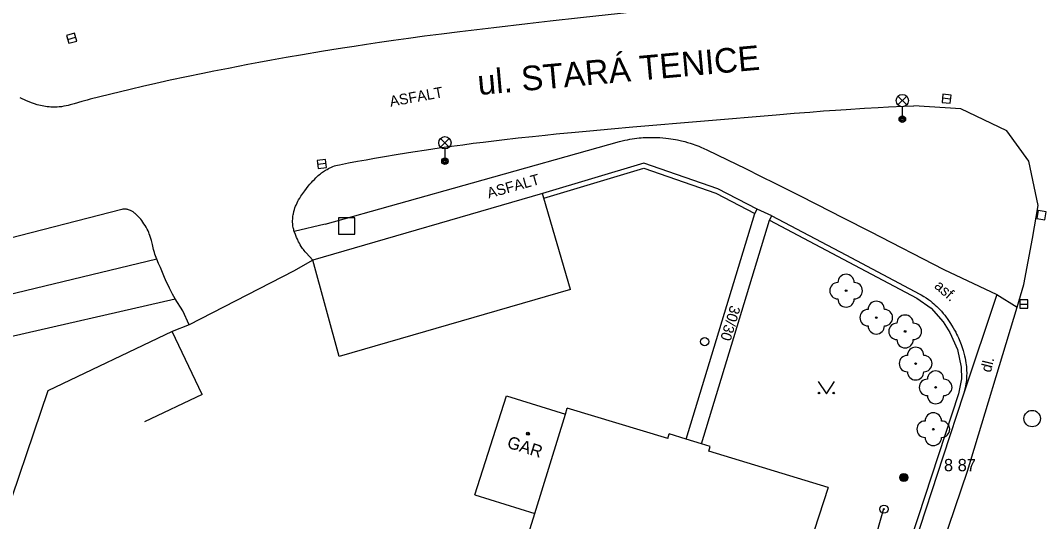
# Model space of a CAD drawing. Extents: x -538441 to -536770, y -1181008 to -1179809.
# Drawn here: x -538155.1 to -538092.8, y -1180657.4 to -1180626.8 of the extents above; entities that cross this region are included whole.
import ezdxf

# ---------------------------------------------------------------- set-up
doc = ezdxf.new("R2010")
doc.units = 0
for name, color, linetype in [('Vrstva 10', 7, 'Continuous'), ('Vrstva 11', 7, 'Continuous'), ('Vrstva 22', 7, 'Continuous'), ('Vrstva 25', 7, 'Continuous'), ('Vrstva 26', 7, 'Continuous'), ('Vrstva 27', 7, 'Continuous'), ('Vrstva 28', 7, 'Continuous'), ('Vrstva 33', 7, 'Continuous'), ('Vrstva 36', 7, 'Continuous'), ('Vrstva 39', 7, 'Continuous'), ('Vrstva 4', 7, 'Continuous'), ('Vrstva 40', 7, 'Continuous'), ('Vrstva 41', 7, 'Continuous'), ('Vrstva 49', 7, 'Continuous'), ('Vrstva 5', 7, 'Continuous'), ('Vrstva 7', 7, 'Continuous'), ('Vrstva 8', 7, 'Continuous')]:
    doc.layers.add(name, color=color, linetype=linetype)

msp = doc.modelspace()

# ---------------------------------------------------------------- linework, layer by layer
at = {"layer": 'Vrstva 10'}
for p, q in [((-538124.117, -1180627.024), (-538126.183, -1180627.265)), ((-538126.183, -1180627.265), (-538128.25, -1180627.51)), ((-538147.54, -1180630.827), (-538148.359, -1180631.023)), ((-538097.687, -1180632.204), (-538100.568, -1180632.016)), ((-538117.69, -1180633.31), (-538108.95, -1180632.561)), ((-538094.88, -1180633.55), (-538097.687, -1180632.204)), ((-538093.553, -1180635.402), (-538094.88, -1180633.55)), ((-538092.977, -1180638.092), (-538093.553, -1180635.402)), ((-538093.316, -1180640.1), (-538092.977, -1180638.092)), ((-538148.87, -1180638.34), (-538156.55, -1180640.32)), ((-538093.84, -1180642.91), (-538093.316, -1180640.1)), ((-538094.26, -1180644.3), (-538093.84, -1180642.91)), ((-538097.28, -1180654.29), (-538094.26, -1180644.3)), ((-538100.376, -1180663.311), (-538097.28, -1180654.29)), ((-538103.09, -1180658.98), (-538102.38, -1180656.57))]:
    msp.add_line(p, q, dxfattribs=at)
for points in [[(-538115.45, -1180626.07), (-538117.051, -1180626.239), (-538118.451, -1180626.389), (-538120.901, -1180626.659), (-538122.739, -1180626.866), (-538124.117, -1180627.024)], [(-538128.25, -1180627.51), (-538129.363, -1180627.647), (-538130.404, -1180627.78), (-538131.38, -1180627.911), (-538132.294, -1180628.038), (-538133.15, -1180628.162), (-538133.953, -1180628.281), (-538134.704, -1180628.395), (-538135.408, -1180628.506), (-538136.068, -1180628.611), (-538136.686, -1180628.712), (-538137.844, -1180628.907)], [(-538137.844, -1180628.907), (-538138.856, -1180629.083), (-538139.741, -1180629.242), (-538140.515, -1180629.384), (-538141.192, -1180629.51), (-538142.375, -1180629.738), (-538143.262, -1180629.913), (-538143.927, -1180630.047), (-538144.924, -1180630.252), (-538145.92, -1180630.462), (-538146.535, -1180630.596), (-538147.071, -1180630.718), (-538147.54, -1180630.827)], [(-538148.359, -1180631.023), (-538150.81, -1180631.62), (-538150.992, -1180631.666), (-538151.31, -1180631.756), (-538151.785, -1180631.895), (-538152.022, -1180631.961), (-538152.141, -1180631.992), (-538152.26, -1180632.02), (-538152.407, -1180632.05), (-538152.549, -1180632.073), (-538152.686, -1180632.088), (-538152.819, -1180632.098), (-538152.948, -1180632.102), (-538153.073, -1180632.102), (-538153.194, -1180632.097), (-538153.311, -1180632.088), (-538153.424, -1180632.076), (-538153.533, -1180632.061), (-538153.639, -1180632.043), (-538153.742, -1180632.024), (-538153.841, -1180632.002), (-538153.937, -1180631.978), (-538154.03, -1180631.953), (-538154.209, -1180631.899), (-538154.377, -1180631.841), (-538154.535, -1180631.781), (-538154.682, -1180631.72), (-538154.819, -1180631.658), (-538154.948, -1180631.597), (-538155.069, -1180631.536)], [(-538108.95, -1180632.561), (-538107.857, -1180632.472), (-538106.901, -1180632.398), (-538106.064, -1180632.336), (-538105.332, -1180632.284), (-538104.691, -1180632.24), (-538103.569, -1180632.169), (-538102.727, -1180632.12), (-538102.095, -1180632.086), (-538101.148, -1180632.04), (-538100.568, -1180632.016)], [(-538133.468, -1180635.215), (-538132.977, -1180635.13), (-538132.024, -1180634.971), (-538131.13, -1180634.828), (-538130.292, -1180634.701), (-538129.507, -1180634.586), (-538128.77, -1180634.483), (-538128.08, -1180634.389), (-538127.432, -1180634.305), (-538126.825, -1180634.228), (-538125.686, -1180634.09), (-538124.688, -1180633.976), (-538123.816, -1180633.881)], [(-538123.816, -1180633.881), (-538123.051, -1180633.8), (-538122.382, -1180633.733), (-538121.211, -1180633.619), (-538120.332, -1180633.537), (-538119.012, -1180633.421), (-538117.69, -1180633.31)], [(-538137.23, -1180641.42), (-538137.43, -1180641.202), (-538137.631, -1180640.983), (-538137.692, -1180640.914), (-538137.747, -1180640.846), (-538137.797, -1180640.781), (-538137.842, -1180640.718), (-538137.923, -1180640.597), (-538137.989, -1180640.488), (-538138.043, -1180640.391), (-538138.089, -1180640.304), (-538138.163, -1180640.151), (-538138.214, -1180640.036), (-538138.286, -1180639.862), (-538138.35, -1180639.69), (-538138.371, -1180639.627), (-538138.389, -1180639.566), (-538138.404, -1180639.506), (-538138.417, -1180639.447), (-538138.437, -1180639.331), (-538138.449, -1180639.22), (-538138.454, -1180639.115), (-538138.455, -1180639.016), (-538138.451, -1180638.922), (-538138.444, -1180638.833), (-538138.434, -1180638.75), (-538138.422, -1180638.672), (-538138.408, -1180638.598), (-538138.377, -1180638.46), (-538138.343, -1180638.34), (-538138.309, -1180638.235), (-538138.275, -1180638.144), (-538138.243, -1180638.065), (-538138.18, -1180637.927), (-538138.129, -1180637.826), (-538138.087, -1180637.75), (-538138.021, -1180637.639), (-538137.95, -1180637.53), (-538137.83, -1180637.357), (-538137.715, -1180637.199), (-538137.606, -1180637.053), (-538137.501, -1180636.921), (-538137.402, -1180636.8), (-538137.307, -1180636.691), (-538137.216, -1180636.591), (-538137.129, -1180636.501), (-538137.047, -1180636.419), (-538136.968, -1180636.344), (-538136.893, -1180636.277), (-538136.821, -1180636.216), (-538136.753, -1180636.161), (-538136.689, -1180636.111), (-538136.565, -1180636.023), (-538136.455, -1180635.951), (-538136.356, -1180635.892), (-538136.267, -1180635.844), (-538136.189, -1180635.805), (-538136.119, -1180635.773), (-538135.994, -1180635.722), (-538135.898, -1180635.688), (-538135.825, -1180635.665), (-538135.714, -1180635.635), (-538135.6, -1180635.61), (-538135.041, -1180635.502), (-538134.5, -1180635.401), (-538133.976, -1180635.305), (-538133.468, -1180635.215)], [(-538144.76, -1180645.36), (-538145.16, -1180644.515), (-538145.61, -1180643.78), (-538145.695, -1180643.637), (-538145.772, -1180643.501), (-538145.841, -1180643.373), (-538145.966, -1180643.129), (-538146.07, -1180642.912), (-538146.158, -1180642.721), (-538146.306, -1180642.384), (-538146.522, -1180641.876), (-538146.63, -1180641.622), (-538146.74, -1180641.37), (-538146.786, -1180641.259), (-538146.825, -1180641.154), (-538146.857, -1180641.055), (-538146.885, -1180640.961), (-538146.933, -1180640.783), (-538147.009, -1180640.469), (-538147.068, -1180640.232), (-538147.118, -1180640.054), (-538147.161, -1180639.922), (-538147.197, -1180639.823), (-538147.226, -1180639.749), (-538147.275, -1180639.639), (-538147.33, -1180639.53), (-538147.394, -1180639.415), (-538147.459, -1180639.305), (-538147.525, -1180639.203), (-538147.59, -1180639.107), (-538147.654, -1180639.018), (-538147.717, -1180638.938), (-538147.778, -1180638.864), (-538147.836, -1180638.797), (-538147.893, -1180638.737), (-538147.948, -1180638.683), (-538148, -1180638.635), (-538148.049, -1180638.592), (-538148.097, -1180638.554), (-538148.142, -1180638.52), (-538148.184, -1180638.491), (-538148.265, -1180638.441), (-538148.338, -1180638.403), (-538148.402, -1180638.375), (-538148.459, -1180638.355), (-538148.509, -1180638.341), (-538148.553, -1180638.331), (-538148.592, -1180638.325), (-538148.661, -1180638.318), (-538148.713, -1180638.318), (-538148.752, -1180638.32), (-538148.811, -1180638.327), (-538148.87, -1180638.34)]]:
    msp.add_lwpolyline(points, dxfattribs=at)
at = {"layer": 'Vrstva 11'}
for p, q in [((-538127.485, -1180636.72), (-538118.51, -1180634.2)), ((-538136.46, -1180639.24), (-538127.485, -1180636.72)), ((-538114.44, -1180652.333), (-538110.258, -1180638.576)), ((-538136.46, -1180639.24), (-538138.35, -1180639.69)), ((-538113.513, -1180652.614), (-538109.37, -1180638.985)), ((-538103.23, -1180639.68), (-538098.735, -1180641.995)), ((-538146.74, -1180641.37), (-538163.67, -1180645.44)), ((-538098.735, -1180641.995), (-538095.49, -1180643.52)), ((-538160.23, -1180647.12), (-538145.61, -1180643.78)), ((-538095.49, -1180643.52), (-538097.53, -1180649.6)), ((-538095.49, -1180643.52), (-538094.26, -1180644.3))]:
    msp.add_line(p, q, dxfattribs=at)
for points in [[(-538118.51, -1180634.2), (-538118.348, -1180634.157), (-538118.19, -1180634.119), (-538118.035, -1180634.085), (-538117.885, -1180634.056), (-538117.738, -1180634.031), (-538117.595, -1180634.01), (-538117.455, -1180633.992), (-538117.32, -1180633.977), (-538117.188, -1180633.965), (-538117.06, -1180633.956), (-538116.936, -1180633.949), (-538116.694, -1180633.941), (-538116.467, -1180633.941), (-538116.254, -1180633.946), (-538116.055, -1180633.956), (-538115.867, -1180633.971), (-538115.692, -1180633.988), (-538115.528, -1180634.008), (-538115.375, -1180634.03), (-538115.232, -1180634.053), (-538115.098, -1180634.076), (-538114.973, -1180634.101), (-538114.739, -1180634.152), (-538114.537, -1180634.202), (-538114.361, -1180634.251), (-538114.209, -1180634.296), (-538114.076, -1180634.339), (-538113.847, -1180634.419), (-538113.677, -1180634.483), (-538113.551, -1180634.534), (-538113.364, -1180634.615), (-538113.18, -1180634.7), (-538111.921, -1180635.311), (-538110.824, -1180635.847), (-538109.869, -1180636.319)], [(-538109.869, -1180636.319), (-538109.035, -1180636.734), (-538107.58, -1180637.463), (-538106.491, -1180638.013), (-538104.86, -1180638.843), (-538103.23, -1180639.68)]]:
    msp.add_lwpolyline(points, dxfattribs=at)
at = {"layer": 'Vrstva 22'}
for centre in [(-538104.69, -1180643.29), (-538102.85, -1180644.93), (-538101.09, -1180645.77), (-538100.45, -1180647.73), (-538099.23, -1180649.18), (-538099.37, -1180651.73)]:
    msp.add_circle(centre, 0.05, dxfattribs=at)
for centre, start, end in [((-538104.69, -1180642.79), 0, 180), ((-538105.19, -1180643.29), 90, 270), ((-538104.19, -1180643.29), 270, 90), ((-538104.69, -1180643.79), 180, 0), ((-538103.35, -1180644.93), 90, 270), ((-538102.85, -1180644.43), 0, 180), ((-538102.35, -1180644.93), 270, 90), ((-538101.09, -1180645.27), 0, 180), ((-538102.85, -1180645.43), 180, 0), ((-538101.59, -1180645.77), 90, 270), ((-538100.59, -1180645.77), 270, 90), ((-538101.09, -1180646.27), 180, 0), ((-538100.45, -1180647.23), 0, 180), ((-538100.95, -1180647.73), 90, 270), ((-538099.95, -1180647.73), 270, 90), ((-538099.23, -1180648.68), 0, 180), ((-538100.45, -1180648.23), 180, 0), ((-538099.73, -1180649.18), 90, 270), ((-538098.73, -1180649.18), 270, 90), ((-538099.23, -1180649.68), 180, 0), ((-538099.87, -1180651.73), 90, 270), ((-538099.37, -1180651.23), 0, 180), ((-538098.87, -1180651.73), 270, 90), ((-538099.37, -1180652.23), 180, 0)]:
    msp.add_arc(centre, 0.5, start, end, dxfattribs=at)
at = {"layer": 'Vrstva 25'}
for centre, radius in [((-538101.17, -1180654.67), 0.25), ((-538101.17, -1180654.67), 0.2), ((-538101.17, -1180654.67), 0.15), ((-538101.17, -1180654.67), 0.1), ((-538101.17, -1180654.67), 0.05), ((-538102.38, -1180656.6), 0.25), ((-538102.38, -1180656.6), 0.0303)]:
    msp.add_circle(centre, radius, dxfattribs=at)
at = {"layer": 'Vrstva 26'}
msp.add_lwpolyline([(-538135.65, -1180639.84), (-538134.65, -1180639.84), (-538134.65, -1180638.84), (-538135.65, -1180638.84)], close=True, dxfattribs=at)
at = {"layer": 'Vrstva 27'}
for p, q in [((-538152.17, -1180627.969), (-538151.69, -1180627.831)), ((-538098.312, -1180631.618), (-538098.808, -1180631.562)), ((-538136.425, -1180635.53), (-538136.921, -1180635.596)), ((-538094.1, -1180644.1), (-538093.6, -1180644.1))]:
    msp.add_line(p, q, dxfattribs=at)
for points in [[(-538152.101, -1180628.209), (-538151.621, -1180628.071), (-538151.759, -1180627.591), (-538152.239, -1180627.729)], [(-538098.283, -1180631.37), (-538098.78, -1180631.313), (-538098.837, -1180631.81), (-538098.34, -1180631.867)], [(-538136.458, -1180635.282), (-538136.954, -1180635.348), (-538136.888, -1180635.844), (-538136.392, -1180635.778)], [(-538092.975, -1180638.392), (-538093.058, -1180638.885), (-538092.565, -1180638.968), (-538092.482, -1180638.475)], [(-538094.1, -1180644.35), (-538093.6, -1180644.35), (-538093.6, -1180643.85), (-538094.1, -1180643.85)]]:
    msp.add_lwpolyline(points, close=True, dxfattribs=at)
msp.add_circle((-538093.34, -1180651.08), 0.5, dxfattribs=at)
at = {"layer": 'Vrstva 28'}
msp.add_circle((-538113.32, -1180646.39), 0.25, dxfattribs=at)
at = {"layer": 'Vrstva 33'}
for p, q in [((-538101.525, -1180631.97), (-538100.995, -1180631.44)), ((-538101.525, -1180631.44), (-538100.995, -1180631.97)), ((-538101.26, -1180632.08), (-538101.26, -1180632.83)), ((-538129.425, -1180634.54), (-538128.895, -1180634.01)), ((-538129.425, -1180634.01), (-538128.895, -1180634.54)), ((-538129.16, -1180634.65), (-538129.16, -1180635.4))]:
    msp.add_line(p, q, dxfattribs=at)
for centre, radius in [((-538101.26, -1180631.705), 0.375), ((-538101.26, -1180632.83), 0.2), ((-538101.26, -1180632.83), 0.145), ((-538101.26, -1180632.83), 0.0876), ((-538129.16, -1180634.275), 0.375), ((-538129.16, -1180635.4), 0.2), ((-538129.16, -1180635.4), 0.145), ((-538129.16, -1180635.4), 0.0876)]:
    msp.add_circle(centre, radius, dxfattribs=at)
at = {"layer": 'Vrstva 36'}
msp.add_lwpolyline([(-538106.396, -1180648.823), (-538105.896, -1180649.573), (-538105.396, -1180648.823)], dxfattribs=at)
for centre in [(-538106.346, -1180649.523), (-538105.447, -1180649.523)]:
    msp.add_circle(centre, 0.05, dxfattribs=at)
at = {"layer": 'Vrstva 39'}
for radius in [0.09, 0.0398]:
    msp.add_circle((-538124.102, -1180652.003), radius, dxfattribs=at)
at = {"layer": 'Vrstva 5'}
for p, q in [((-538123.22, -1180637.37), (-538137.23, -1180641.42)), ((-538123.137, -1180637.658), (-538123.22, -1180637.37)), ((-538121.512, -1180643.215), (-538123.137, -1180637.658)), ((-538135.61, -1180647.29), (-538137.23, -1180641.42)), ((-538121.512, -1180643.215), (-538135.61, -1180647.29)), ((-538145.809, -1180645.774), (-538153.39, -1180649.39)), ((-538143.98, -1180649.61), (-538145.809, -1180645.774)), ((-538153.39, -1180649.39), (-538159.277, -1180666.733)), ((-538143.98, -1180649.61), (-538147.498, -1180651.288)), ((-538127.34, -1180655.72), (-538125.41, -1180649.7)), ((-538125.41, -1180649.7), (-538121.816, -1180650.822)), ((-538121.816, -1180650.822), (-538121.7, -1180650.44)), ((-538115.573, -1180652.303), (-538121.7, -1180650.44)), ((-538115.573, -1180652.303), (-538115.485, -1180652.015)), ((-538114.44, -1180652.333), (-538115.485, -1180652.015)), ((-538113.513, -1180652.614), (-538114.44, -1180652.333)), ((-538112.985, -1180652.775), (-538113.513, -1180652.614)), ((-538113.073, -1180653.063), (-538112.985, -1180652.775)), ((-538105.78, -1180655.28), (-538113.073, -1180653.063)), ((-538105.78, -1180655.28), (-538113.83, -1180679.89)), ((-538127.34, -1180655.72), (-538123.683, -1180656.862))]:
    msp.add_line(p, q, dxfattribs=at)
msp.add_lwpolyline([(-538124.57, -1180659.73), (-538123.683, -1180656.862), (-538121.816, -1180650.822)], dxfattribs=at)
at = {"layer": 'Vrstva 7'}
for p, q in [((-538117.02, -1180635.51), (-538123.22, -1180637.37)), ((-538123.137, -1180637.658), (-538117.027, -1180635.825)), ((-538109.37, -1180638.985), (-538104.871, -1180641.364)), ((-538104.871, -1180641.364), (-538100.373, -1180643.743)), ((-538104.71, -1180641.11), (-538100.19, -1180643.5)), ((-538137.23, -1180641.42), (-538138.41, -1180642.1)), ((-538100.19, -1180643.5), (-538100.106, -1180643.545)), ((-538100.106, -1180643.545), (-538099.948, -1180643.638)), ((-538099.948, -1180643.638), (-538099.803, -1180643.73)), ((-538099.803, -1180643.73), (-538099.671, -1180643.822)), ((-538099.671, -1180643.822), (-538099.551, -1180643.911)), ((-538099.551, -1180643.911), (-538099.44, -1180643.999)), ((-538099.44, -1180643.999), (-538099.339, -1180644.084)), ((-538099.339, -1180644.084), (-538099.247, -1180644.166)), ((-538099.247, -1180644.166), (-538099.162, -1180644.246)), ((-538099.162, -1180644.246), (-538099.083, -1180644.323)), ((-538099.083, -1180644.323), (-538099.011, -1180644.397)), ((-538099.011, -1180644.397), (-538098.879, -1180644.54)), ((-538098.879, -1180644.54), (-538098.767, -1180644.669)), ((-538098.767, -1180644.669), (-538098.672, -1180644.787)), ((-538098.672, -1180644.787), (-538098.591, -1180644.892)), ((-538098.591, -1180644.892), (-538098.521, -1180644.986)), ((-538098.521, -1180644.986), (-538098.402, -1180645.156)), ((-538144.76, -1180645.36), (-538145.809, -1180645.774)), ((-538098.402, -1180645.156), (-538098.316, -1180645.287)), ((-538098.316, -1180645.287), (-538098.253, -1180645.388)), ((-538098.253, -1180645.388), (-538098.16, -1180645.542)), ((-538098.16, -1180645.542), (-538098.07, -1180645.7)), ((-538098.07, -1180645.7), (-538098.006, -1180645.818)), ((-538098.006, -1180645.818), (-538097.947, -1180645.933)), ((-538097.947, -1180645.933), (-538097.892, -1180646.044)), ((-538097.892, -1180646.044), (-538097.841, -1180646.154)), ((-538097.841, -1180646.154), (-538097.794, -1180646.26)), ((-538097.794, -1180646.26), (-538097.75, -1180646.363)), ((-538097.75, -1180646.363), (-538097.671, -1180646.564)), ((-538097.671, -1180646.564), (-538097.604, -1180646.754)), ((-538097.604, -1180646.754), (-538097.548, -1180646.933)), ((-538097.548, -1180646.933), (-538097.501, -1180647.101)), ((-538097.501, -1180647.101), (-538097.462, -1180647.26)), ((-538097.462, -1180647.26), (-538097.43, -1180647.408)), ((-538097.43, -1180647.408), (-538097.404, -1180647.548)), ((-538097.404, -1180647.548), (-538097.383, -1180647.678)), ((-538097.383, -1180647.678), (-538097.367, -1180647.801)), ((-538097.367, -1180647.801), (-538097.355, -1180647.916)), ((-538097.355, -1180647.916), (-538097.346, -1180648.023)), ((-538097.346, -1180648.023), (-538097.34, -1180648.124)), ((-538097.34, -1180648.124), (-538097.335, -1180648.313)), ((-538097.353, -1180648.745), (-538097.365, -1180648.853)), ((-538097.343, -1180648.62), (-538097.353, -1180648.745)), ((-538097.336, -1180648.477), (-538097.343, -1180648.62)), ((-538097.335, -1180648.313), (-538097.336, -1180648.477)), ((-538097.405, -1180649.113), (-538097.53, -1180649.6)), ((-538097.378, -1180648.948), (-538097.405, -1180649.113)), ((-538097.365, -1180648.853), (-538097.378, -1180648.948)), ((-538097.837, -1180649.572), (-538100.302, -1180657.074)), ((-538097.53, -1180649.6), (-538098.766, -1180653.367)), ((-538098.766, -1180653.367), (-538100.625, -1180659.018)), ((-538100.302, -1180657.074), (-538102.765, -1180664.577))]:
    msp.add_line(p, q, dxfattribs=at)
for points in [[(-538110.258, -1180638.576), (-538110.12, -1180638.31), (-538112.51, -1180637.07), (-538117.02, -1180635.51)], [(-538117.027, -1180635.825), (-538112.629, -1180637.346), (-538110.258, -1180638.576)], [(-538109.37, -1180638.985), (-538109.23, -1180638.72), (-538104.71, -1180641.11)], [(-538100.373, -1180643.743), (-538099.493, -1180644.361), (-538098.765, -1180645.184), (-538098.354, -1180645.838), (-538097.898, -1180646.876), (-538097.671, -1180647.944), (-538097.66, -1180648.653), (-538097.837, -1180649.572)]]:
    msp.add_lwpolyline(points, dxfattribs=at)
at = {"layer": 'Vrstva 8'}
for p, q in [((-538109.23, -1180638.72), (-538110.12, -1180638.31)), ((-538138.41, -1180642.1), (-538144.76, -1180645.36))]:
    msp.add_line(p, q, dxfattribs=at)

# ---------------------------------------------------------------- texts
at = {"layer": 'Vrstva 4'}
msp.add_text(' 8 87', height=0.75, dxfattribs=at).set_placement((-538098.999, -1180654.29))
at = {"layer": 'Vrstva 40'}
for s, rotation, p in [('ASFALT', 10.32496, (-538132.475, -1180632.079)), ('ASFALT', 15.68368, (-538126.491, -1180637.669)), ('asf.', 318.85239, (-538099.356, -1180643.069)), ('30/30', 253.09121, (-538111.741, -1180644.138)), ('dl.', 76.25012, (-538095.863, -1180648.306))]:
    msp.add_text(s, height=0.65, rotation=rotation, dxfattribs=at).set_placement(p)
at = {"layer": 'Vrstva 41'}
msp.add_text('GAR', height=0.75, rotation=342.66231, dxfattribs=at).set_placement((-538125.423, -1180652.839))
at = {"layer": 'Vrstva 49'}
msp.add_text('ul. STARÁ TENICE', height=1.5, rotation=5.15559, dxfattribs=at).set_placement((-538127.109, -1180631.366))

doc.saveas('drawing.dxf')
